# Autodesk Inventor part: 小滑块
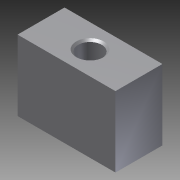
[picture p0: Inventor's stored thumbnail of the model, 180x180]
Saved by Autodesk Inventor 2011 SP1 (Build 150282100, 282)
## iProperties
Created: 2013-12
Part Number: 小滑块
Document SubType Name: Modeling
Designer: Administrator
Density: 1 g/cm^3
Author: Administrator
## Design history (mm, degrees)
sketch "草图1"
  geometry: L1 (-12.5, 6)-(12.5, 6); L2 (12.5, 6)-(12.5, -6); L3 (12.5, -6)-(-12.5, -6); L4 (-12.5, -6)-(-12.5, 6); 3 further points
  constraints: 8 end point, 2 midpoint, 2 parallel, 1 horizontal, 1 horizontal alignment, 1 perpendicular, 1 vertical alignment
  dimensions: "d0" = 25 distance of L2.end L3.end; "d1" = 12 distance of L3.end L1.start
extrude "拉伸1" new body sketch "草图1" distance "d2" = 18; taper "d3" = 0 deg
sketch "草图2"
  geometry: 2 further points
  constraints: 1 coincident
hole "Hole1" sketch "草图2" at (0, 0) diameter "d4" = 6; stored, may be unused: countersink angle "d8" = 90 deg, drill point angle "d10" = 118 deg; dims "d5" = 6, "d6" = 4, "d7" = 2, "d9" = 8
chamfer "倒角1" distance "d11" = 0.5; stored, may be unused: second distance "d12" = 2, angle "d13" = 45 deg
node "实体1"
